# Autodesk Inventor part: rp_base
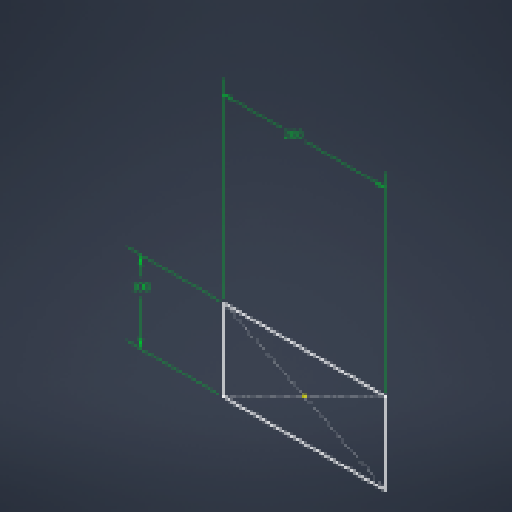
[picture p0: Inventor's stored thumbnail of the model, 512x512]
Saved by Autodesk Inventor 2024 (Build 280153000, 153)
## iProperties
Created: 2023-09
Part Number: rp_base
Material: Generic
Document SubType Name: Modeling
Designer: mammothbane
Density: 1 g/cm^3
Appearance: Default
Author: mammothbane
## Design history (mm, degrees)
sketch "sk_base"
  geometry: L1 (-100, 50)-(100, 50); L2 (100, 50)-(100, -50); L3 (100, -50)-(-100, -50); L4 (-100, -50)-(-100, 50); L5 (-100, 50)-(100, -50); L6 (100, 50)-(-100, -50); 1 further point
  constraints: 12 end point, 2 midpoint, 2 parallel, 1 horizontal, 1 perpendicular
  dimensions: "d0" = 200 distance between parallel lines of L4 L2; "d1" = 100 distance between parallel lines of L3 L1
extrude "Extrusion1" new body sketch "sk_base" distance "d2" = 50; taper "d3" = 0 deg
body "Solid1"
